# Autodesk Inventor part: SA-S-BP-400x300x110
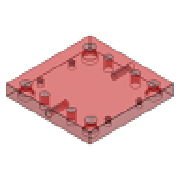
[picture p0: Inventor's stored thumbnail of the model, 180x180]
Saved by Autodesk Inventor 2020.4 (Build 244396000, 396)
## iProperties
Created: 2019-01
Part Number: SA-S-BP-400x300x110
Material: S 55 C
Description: Core Plate
Document SubType Name: Modeling
Designer: mel
Standard Revision: 1
Manufacturer: FUTABA
Language: fr-FR
Size Designation: 400x300x110
Categories: <MemberInstance><Categories><Category DisplayName="Moule" InternalName="349578f2-f4d4-4954-8c09-8e99297a61c0" Mnemonic="MOLD"><Category DisplayName="Plaque de m
Density: 7.85 g/cm^3
Appearance: Dark Red
IsCustomPart: 1
Author: mel
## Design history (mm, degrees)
sketch "Sketch1"
  geometry: L1 (-150, 200)-(150, 200); L2 (150, 200)-(150, -200); L3 (150, -200)-(-150, -200); L4 (-150, -200)-(-150, 200); 7 further points
  constraints: 8 end point, 2 horizontal alignment, 2 midpoint, 2 parallel, 1 horizontal, 1 perpendicular, 1 vertical alignment
  dimensions: "d123" = 300 distance between parallel lines of L2 L4 (= W_); "d124" = 400 distance between parallel lines of L3 L1 (= L); "d125" = 170 vertical distance of point (0, 0) point (-67, 170) (= 0.5 x RP_L); "d126" = 67 horizontal distance of point (0, 0) point (-67, 170) (= 0.5 x RP_W); "d127" = 117 horizontal distance of point (0, 0) point (-117, 167) (= 0.5 x GP_W); "d128" = 167 vertical distance of point (0, 0) point (-117, 167) (= 0.5 x GP_L); "d129" = 120 horizontal distance of point (0, 0) point (-120, 119) (= 0.5 x S1_W); "d130" = 119 vertical distance of point (0, 0) point (-120, 119) (= 0.5 x S1_L); "d140" = 117 horizontal distance of point (117, 167) point (0, 0) (= 0.5 x GP_W)
extrude "Extrusion1" new body sketch "Sketch1" distance "d20" = 110 (= H_); taper "d30" = 0 deg
sketch "Sketch2"
  geometry: L1 (300, 0)-(0, 0) reference; 3 further points
  constraints: 1 midpoint, 1 vertical alignment
  dimensions: "d186" = 55 distance from line of L1 point (150, 55) (= 0.5 x H_)
hole "Hole1" sketch "Sketch2" at (150, 55) diameter "d104" = 17.294; stored, may be unused: countersink angle "d108" = 90 deg, drill point angle "d110" = 118 deg; dims "d105" = 33 (= le), "d106" = 36 (= GP_d2), "d107" = 8 (= GP_k), "d109" = 46 (= ke)
sketch "Sketch3"
  geometry: L1 (0, 0)-(300, 0) reference; 3 further points
  constraints: 1 midpoint, 1 vertical alignment
  dimensions: "d187" = 55 distance from line of point (150, -55) L1 (= 0.5 x H_)
hole "Hole2" sketch "Sketch3" at (150, -55) diameter "d113" = 17.294; stored, may be unused: countersink angle "d117" = 90 deg, drill point angle "d119" = 118 deg; dims "d114" = 33 (= le), "d115" = 36 (= GP_d2), "d116" = 8 (= GP_k), "d118" = 46 (= ke)
hole "Hole3" sketch "Sketch1" diameter "d131" = 11.835; stored, may be unused: countersink angle "d135" = 90 deg, drill point angle "d137" = 118 deg; dims "d132" = 18 (= H_l), "d133" = 4, "d134" = 2, "d136" = 28 (= H_u)
pattern_linear "Rectangular Pattern1" dims "d164" = 119 (computed from S1_L, Ns), "d167" = 240 (computed from S1_W, Nw)
hole "Hole4" sketch "Sketch1" diameter "d141" = 30 (= GP_d1); stored, may be unused: countersink angle "d145" = 90 deg, drill point angle "d147" = 0 deg; dims "d142" = 6, "d143" = 36 (= GP_d2), "d144" = 8 (= GP_k), "d146" = 110 (= H_)
pattern_linear "Rectangular Pattern2" dims "d170" = 334 (computed from GP_L, Nl)
hole "Hole5" sketch "Sketch1" diameter "d148" = 30 (= GP_d1); stored, may be unused: countersink angle "d152" = 90 deg, drill point angle "d154" = 0 deg; dims "d149" = 6, "d150" = 36 (= GP_d2), "d151" = 8 (= GP_k), "d153" = 110 (= H_)
pattern_linear "Rectangular Pattern3" dims "d173" = 332 (computed from GP_L2, GP_L1, Nl)
hole "Hole6" sketch "Sketch1" diameter "d155" = 20 (= RP_dt); stored, may be unused: countersink angle "d159" = 90 deg, drill point angle "d161" = 0 deg; dims "d156" = 6, "d157" = 36 (= GP_d2), "d158" = 8 (= GP_k), "d160" = 110 (= H_)
pattern_linear "Rectangular Pattern4" dims "d176" = 340 (computed from RP_L, Nl), "d179" = 134 (computed from RP_W, Nw)
chamfer "Chamfer1" distance "d180" = 0.5; stored, may be unused: second distance "d181" = 2, angle "d182" = 45 deg
feature "Sculpter1"
body "Solid1"
feature "Surface1"
body "Srf1"
other parameters: "L" = 400 [user parameter; used in 1 equation term], "W_" = 300 [user parameter; used in 3 equation terms], "H_" = 110 [user parameter; used in 8 equation terms], "GP_W" = 234 [user parameter; used in 2 equation terms], "GP_d1" = 30 [user parameter; used in 2 equation terms], "GP_d2" = 36 [user parameter; used in 5 equation terms], "GP_k" = 8 [user parameter; used in 5 equation terms], "S1_L" = 238 [user parameter; used in 2 equation terms], "GP_L1" = 167 [user parameter; used in 1 equation term], "GP_L2" = 165 [user parameter; used in 1 equation term], "RP_W" = 134 [user parameter; used in 2 equation terms], "RP_dt" = 20 [user parameter; used in 1 equation term], "GP_L" = 334 [user parameter; used in 2 equation terms], "d102" = 55 (= 0.5 x H_), "d112" = 55 (= 0.5 x H_), "le" = 33 [user parameter; used in 2 equation terms], "ke" = 46 [user parameter; used in 2 equation terms], "H_l" = 18 [user parameter; used in 1 equation term], "H_u" = 28 [user parameter; used in 1 equation term]
